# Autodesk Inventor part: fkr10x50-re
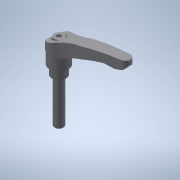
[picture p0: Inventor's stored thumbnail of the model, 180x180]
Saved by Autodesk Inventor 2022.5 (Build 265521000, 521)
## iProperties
Created: 2017-09
Part Number: fkr10x50-re
Material: 一般
Document SubType Name: Modeling
Designer: imaocorp
Density: 1 g/cm^3
Appearance: 既定
Author: imaocorp
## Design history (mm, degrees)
node "fkr10x50-re.x_t1"
node "fkr10x50-re"
node "Base1"
